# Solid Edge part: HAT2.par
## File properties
Author: Andrea Rangi V
Template: Ansi Metric part.par
Last saved by: Andrea Rangi V
Revision: 4
Application: Solid Edge
Accuracy: 0.990
Username: Andrea Rangi V
Face Style: Model Default
Coef. of Thermal Exp: 0.0
Thermal Conductivity: 0.0
Specific Heat: 0.0
Modulus of Elasticity: 0.0
Poisson's Ratio: 0.0
Yield Stress: 0.0
Ultimate Stress: 0.0
Elongation: 0.0
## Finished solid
Body 1: solid body, 72 faces, 210 edges, 140 vertices.
  Faces by surface: plane 72
  Edges by curve: line 210
Bounding box of the edges (mm): 180.000 x 3.000 x 270.000, from (-71.1238, 0, -126.1621) to (108.8762, 3, 143.8379).
Planar faces by outward normal: +x 17, +y 1, +z 18, -x 18, -y 1, -z 17
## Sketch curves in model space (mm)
line (-68.1238, 0, 143.8379) -> (-51.1238, 0, 143.8379)
line (-21.1238, 0, -126.1621) -> (-41.1238, 0, -126.1621)
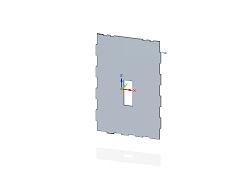
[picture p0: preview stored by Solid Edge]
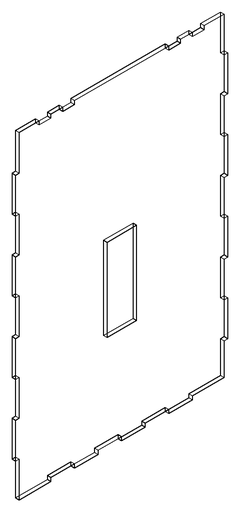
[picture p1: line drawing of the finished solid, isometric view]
